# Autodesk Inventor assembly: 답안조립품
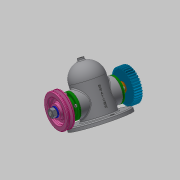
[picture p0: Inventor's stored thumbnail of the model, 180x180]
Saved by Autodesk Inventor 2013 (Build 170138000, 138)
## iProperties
Created: 2019-11
Part Number: 답안조립품
Document SubType Name: Assembly
Designer: Administrator
Author: Administrator
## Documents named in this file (14)
- C:\Users\Administrator\Desktop\491104V1005\답안조립품.iam
- C:\Users\Administrator\Desktop\491104V1005\V-벨트풀리.ipt
- V-벨트풀리.ipt
- C:\Users\Administrator\Desktop\491104V1005\너트 M12x1.25.ipt
- C:\Users\Administrator\Desktop\491104V1005\베어링 6203.ipt
- C:\Users\Administrator\Desktop\491104V1005\본체.ipt
- C:\Users\Administrator\Desktop\491104V1005\볼트 M4.ipt
- C:\Users\Administrator\Desktop\491104V1005\부시.ipt
- C:\Users\Administrator\Desktop\491104V1005\스퍼기어.ipt
- C:\Users\Administrator\Desktop\491104V1005\오일 실 26 38 8.ipt
- C:\Users\Administrator\Desktop\491104V1005\와셔 12x24.ipt
- C:\Users\Administrator\Desktop\491104V1005\축.ipt
- C:\Users\Administrator\Desktop\491104V1005\커버.ipt
- C:\Users\Administrator\Desktop\491104V1005\키 5x5x12.ipt
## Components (1 placed, 1 different names)
1. V-벨트풀리:1
